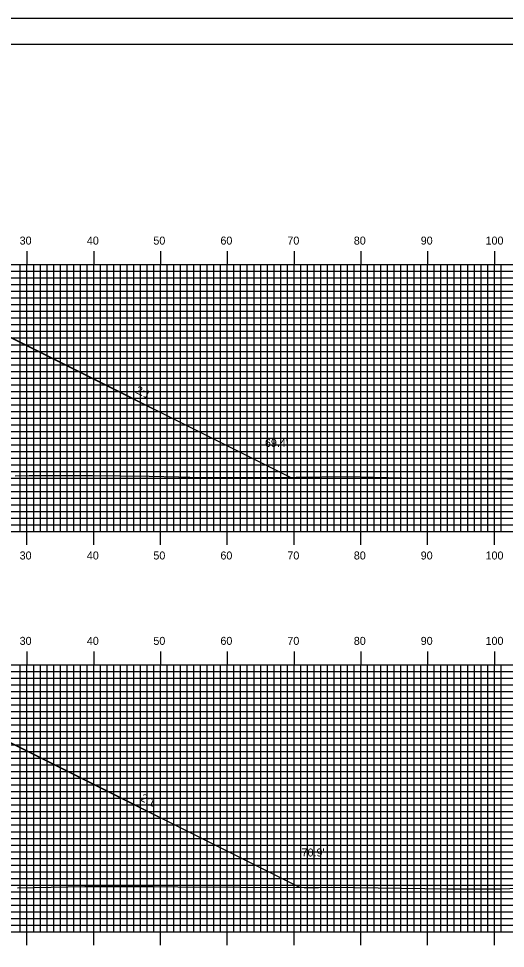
# Model space of a CAD drawing. Extents: x 1809800 to 1810143, y 442591 to 442811.
# Drawn here: x 1809994.1 to 1810067, y 442671.2 to 442810.5 of the extents above; entities that cross this region are included whole.
import ezdxf

# ---------------------------------------------------------------- set-up
doc = ezdxf.new("R2010")
doc.units = 0
for name, color, linetype in [('ANNOTATION', 7, 'Continuous'), ('BORDER', 7, 'Continuous'), ('D_Roadway_Centerline', 7, 'Continuous'), ('D_Roadway_SlopeLines', 7, 'Continuous'), ('D_Text_Standard', 7, 'Continuous'), ('H_V ANNOTATION', 7, 'Continuous'), ('MAJOR', 7, 'Continuous'), ('MINOR', 7, 'Continuous'), ('PLOT BOUNDARY', 7, 'Continuous'), ('S_Roadway_Centerline', 7, 'Continuous')]:
    doc.layers.add(name, color=color, linetype=linetype)

msp = doc.modelspace()

# ---------------------------------------------------------------- linework, layer by layer
at = {"layer": 'BORDER'}
msp.add_lwpolyline([(1809815.75, 442596.67), (1810135.75, 442596.67), (1810135.75, 442806.67), (1809815.75, 442806.67)], close=True, dxfattribs=at)
at = {"layer": 'D_Roadway_Centerline'}
for points in [[(1809892.44, 442741.52), (1809937.14, 442763.87), (1809942.35, 442766.48), (1809945.35, 442766.54), (1809953.35, 442766.7), (1809965.35, 442766.12), (1809977.35, 442765.54), (1809985.35, 442765.16), (1809988.35, 442765.02), (1809993.88, 442762.25), (1810034.75, 442741.82)], [(1809890.34, 442679.72), (1809937.14, 442703.12), (1809942.35, 442705.73), (1809945.35, 442705.79), (1809953.35, 442705.95), (1809965.35, 442705.37), (1809977.35, 442704.79), (1809985.35, 442704.41), (1809988.35, 442704.27), (1809993.88, 442701.5), (1810036.24, 442680.32)]]:
    msp.add_lwpolyline(points, dxfattribs=at)
at = {"layer": 'D_Roadway_SlopeLines'}
for points in [[(1809988.35, 442765.02), (1810034.75, 442741.82)], [(1809988.35, 442704.27), (1810036.24, 442680.32)]]:
    msp.add_lwpolyline(points, dxfattribs=at)
at = {"layer": 'MAJOR'}
for p, q in [((1809995.35, 442775.67), (1809995.35, 442773.67)), ((1810005.35, 442775.67), (1810005.35, 442773.67)), ((1810015.35, 442775.67), (1810015.35, 442773.67)), ((1810025.35, 442775.67), (1810025.35, 442773.67)), ((1810035.35, 442775.67), (1810035.35, 442773.67)), ((1810045.35, 442775.67), (1810045.35, 442773.67)), ((1810055.35, 442775.67), (1810055.35, 442773.67)), ((1810065.35, 442775.67), (1810065.35, 442773.67)), ((1809825.35, 442773.67), (1810105.35, 442773.67)), ((1809825.35, 442773.67), (1810105.35, 442773.67)), ((1809995.35, 442733.67), (1809995.35, 442773.67)), ((1810005.35, 442733.67), (1810005.35, 442773.67)), ((1810015.35, 442733.67), (1810015.35, 442773.67)), ((1810025.35, 442733.67), (1810025.35, 442773.67)), ((1810035.35, 442733.67), (1810035.35, 442773.67)), ((1810045.35, 442733.67), (1810045.35, 442773.67)), ((1810055.35, 442733.67), (1810055.35, 442773.67)), ((1810065.35, 442733.67), (1810065.35, 442773.67)), ((1809825.35, 442768.67), (1810105.35, 442768.67)), ((1809825.35, 442763.67), (1810105.35, 442763.67)), ((1809825.35, 442758.67), (1810105.35, 442758.67)), ((1809825.35, 442753.67), (1810105.35, 442753.67)), ((1809825.35, 442748.67), (1810105.35, 442748.67)), ((1809825.35, 442743.67), (1810105.35, 442743.67)), ((1809825.35, 442738.67), (1810105.35, 442738.67)), ((1809825.35, 442733.67), (1810105.35, 442733.67)), ((1809825.35, 442733.67), (1810105.35, 442733.67)), ((1809995.35, 442731.66), (1809995.35, 442733.67)), ((1810005.35, 442731.66), (1810005.35, 442733.67)), ((1810015.35, 442731.66), (1810015.35, 442733.67)), ((1810025.35, 442731.66), (1810025.35, 442733.67)), ((1810035.35, 442731.66), (1810035.35, 442733.67)), ((1810045.35, 442731.66), (1810045.35, 442733.67)), ((1810055.35, 442731.66), (1810055.35, 442733.67)), ((1810065.35, 442731.66), (1810065.35, 442733.67)), ((1809995.35, 442715.67), (1809995.35, 442713.67)), ((1810005.35, 442715.67), (1810005.35, 442713.67)), ((1810015.35, 442715.67), (1810015.35, 442713.67)), ((1810025.35, 442715.67), (1810025.35, 442713.67)), ((1810035.35, 442715.67), (1810035.35, 442713.67)), ((1810045.35, 442715.67), (1810045.35, 442713.67)), ((1810055.35, 442715.67), (1810055.35, 442713.67)), ((1810065.35, 442715.67), (1810065.35, 442713.67)), ((1809825.35, 442713.67), (1810105.35, 442713.67)), ((1809825.35, 442713.67), (1810105.35, 442713.67)), ((1809995.35, 442673.67), (1809995.35, 442713.67)), ((1810005.35, 442673.67), (1810005.35, 442713.67)), ((1810015.35, 442673.67), (1810015.35, 442713.67)), ((1810025.35, 442673.67), (1810025.35, 442713.67)), ((1810035.35, 442673.67), (1810035.35, 442713.67)), ((1810045.35, 442673.67), (1810045.35, 442713.67)), ((1810055.35, 442673.67), (1810055.35, 442713.67)), ((1810065.35, 442673.67), (1810065.35, 442713.67)), ((1809825.35, 442708.67), (1810105.35, 442708.67)), ((1809825.35, 442703.67), (1810105.35, 442703.67)), ((1809825.35, 442698.67), (1810105.35, 442698.67)), ((1809825.35, 442693.67), (1810105.35, 442693.67)), ((1809825.35, 442688.67), (1810105.35, 442688.67)), ((1809825.35, 442683.67), (1810105.35, 442683.67)), ((1809825.35, 442678.67), (1810105.35, 442678.67)), ((1809825.35, 442673.67), (1810105.35, 442673.67)), ((1809825.35, 442673.67), (1810105.35, 442673.67)), ((1809995.35, 442671.66), (1809995.35, 442673.67)), ((1810005.35, 442671.66), (1810005.35, 442673.67)), ((1810015.35, 442671.66), (1810015.35, 442673.67)), ((1810025.35, 442671.66), (1810025.35, 442673.67)), ((1810035.35, 442671.66), (1810035.35, 442673.67)), ((1810045.35, 442671.66), (1810045.35, 442673.67)), ((1810055.35, 442671.66), (1810055.35, 442673.67)), ((1810065.35, 442671.66), (1810065.35, 442673.67))]:
    msp.add_line(p, q, dxfattribs=at)
at = {"layer": 'MINOR'}
for p, q in [((1809994.35, 442733.67), (1809994.35, 442773.67)), ((1809996.35, 442733.67), (1809996.35, 442773.67)), ((1809997.35, 442733.67), (1809997.35, 442773.67)), ((1809998.35, 442733.67), (1809998.35, 442773.67)), ((1809999.35, 442733.67), (1809999.35, 442773.67)), ((1810000.35, 442733.67), (1810000.35, 442773.67)), ((1810001.35, 442733.67), (1810001.35, 442773.67)), ((1810002.35, 442733.67), (1810002.35, 442773.67)), ((1810003.35, 442733.67), (1810003.35, 442773.67)), ((1810004.35, 442733.67), (1810004.35, 442773.67)), ((1810006.35, 442733.67), (1810006.35, 442773.67)), ((1810007.35, 442733.67), (1810007.35, 442773.67)), ((1810008.35, 442733.67), (1810008.35, 442773.67)), ((1810009.35, 442733.67), (1810009.35, 442773.67)), ((1810010.35, 442733.67), (1810010.35, 442773.67)), ((1810011.35, 442733.67), (1810011.35, 442773.67)), ((1810012.35, 442733.67), (1810012.35, 442773.67)), ((1810013.35, 442733.67), (1810013.35, 442773.67)), ((1810014.35, 442733.67), (1810014.35, 442773.67)), ((1810016.35, 442733.67), (1810016.35, 442773.67)), ((1810017.35, 442733.67), (1810017.35, 442773.67)), ((1810018.35, 442733.67), (1810018.35, 442773.67)), ((1810019.35, 442733.67), (1810019.35, 442773.67)), ((1810020.35, 442733.67), (1810020.35, 442773.67)), ((1810021.35, 442733.67), (1810021.35, 442773.67)), ((1810022.35, 442733.67), (1810022.35, 442773.67)), ((1810023.35, 442733.67), (1810023.35, 442773.67)), ((1810024.35, 442733.67), (1810024.35, 442773.67)), ((1810026.35, 442733.67), (1810026.35, 442773.67)), ((1810027.35, 442733.67), (1810027.35, 442773.67)), ((1810028.35, 442733.67), (1810028.35, 442773.67)), ((1810029.35, 442733.67), (1810029.35, 442773.67)), ((1810030.35, 442733.67), (1810030.35, 442773.67)), ((1810031.35, 442733.67), (1810031.35, 442773.67)), ((1810032.35, 442733.67), (1810032.35, 442773.67)), ((1810033.35, 442733.67), (1810033.35, 442773.67)), ((1810034.35, 442733.67), (1810034.35, 442773.67)), ((1810036.35, 442733.67), (1810036.35, 442773.67)), ((1810037.35, 442733.67), (1810037.35, 442773.67)), ((1810038.35, 442733.67), (1810038.35, 442773.67)), ((1810039.35, 442733.67), (1810039.35, 442773.67)), ((1810040.35, 442733.67), (1810040.35, 442773.67)), ((1810041.35, 442733.67), (1810041.35, 442773.67)), ((1810042.35, 442733.67), (1810042.35, 442773.67)), ((1810043.35, 442733.67), (1810043.35, 442773.67)), ((1810044.35, 442733.67), (1810044.35, 442773.67)), ((1810046.35, 442733.67), (1810046.35, 442773.67)), ((1810047.35, 442733.67), (1810047.35, 442773.67)), ((1810048.35, 442733.67), (1810048.35, 442773.67)), ((1810049.35, 442733.67), (1810049.35, 442773.67)), ((1810050.35, 442733.67), (1810050.35, 442773.67)), ((1810051.35, 442733.67), (1810051.35, 442773.67)), ((1810052.35, 442733.67), (1810052.35, 442773.67)), ((1810053.35, 442733.67), (1810053.35, 442773.67)), ((1810054.35, 442733.67), (1810054.35, 442773.67)), ((1810056.35, 442733.67), (1810056.35, 442773.67)), ((1810057.35, 442733.67), (1810057.35, 442773.67)), ((1810058.35, 442733.67), (1810058.35, 442773.67)), ((1810059.35, 442733.67), (1810059.35, 442773.67)), ((1810060.35, 442733.67), (1810060.35, 442773.67)), ((1810061.35, 442733.67), (1810061.35, 442773.67)), ((1810062.35, 442733.67), (1810062.35, 442773.67)), ((1810063.35, 442733.67), (1810063.35, 442773.67)), ((1810064.35, 442733.67), (1810064.35, 442773.67)), ((1810066.35, 442733.67), (1810066.35, 442773.67)), ((1809825.35, 442772.67), (1810105.35, 442772.67)), ((1809825.35, 442771.67), (1810105.35, 442771.67)), ((1809825.35, 442770.67), (1810105.35, 442770.67)), ((1809825.35, 442769.67), (1810105.35, 442769.67)), ((1809825.35, 442767.67), (1810105.35, 442767.67)), ((1809825.35, 442766.67), (1810105.35, 442766.67)), ((1809825.35, 442765.67), (1810105.35, 442765.67)), ((1809825.35, 442764.67), (1810105.35, 442764.67)), ((1809825.35, 442762.67), (1810105.35, 442762.67)), ((1809825.35, 442761.67), (1810105.35, 442761.67)), ((1809825.35, 442760.67), (1810105.35, 442760.67)), ((1809825.35, 442759.67), (1810105.35, 442759.67)), ((1809825.35, 442757.67), (1810105.35, 442757.67)), ((1809825.35, 442756.67), (1810105.35, 442756.67)), ((1809825.35, 442755.67), (1810105.35, 442755.67)), ((1809825.35, 442754.67), (1810105.35, 442754.67)), ((1809825.35, 442752.67), (1810105.35, 442752.67)), ((1809825.35, 442751.67), (1810105.35, 442751.67)), ((1809825.35, 442750.67), (1810105.35, 442750.67)), ((1809825.35, 442749.67), (1810105.35, 442749.67)), ((1809825.35, 442747.67), (1810105.35, 442747.67)), ((1809825.35, 442746.67), (1810105.35, 442746.67)), ((1809825.35, 442745.67), (1810105.35, 442745.67)), ((1809825.35, 442744.67), (1810105.35, 442744.67)), ((1809825.35, 442742.67), (1810105.35, 442742.67)), ((1809825.35, 442741.67), (1810105.35, 442741.67)), ((1809825.35, 442740.67), (1810105.35, 442740.67)), ((1809825.35, 442739.67), (1810105.35, 442739.67)), ((1809825.35, 442737.67), (1810105.35, 442737.67)), ((1809825.35, 442736.67), (1810105.35, 442736.67)), ((1809825.35, 442735.67), (1810105.35, 442735.67)), ((1809825.35, 442734.67), (1810105.35, 442734.67)), ((1809994.35, 442673.67), (1809994.35, 442713.67)), ((1809996.35, 442673.67), (1809996.35, 442713.67)), ((1809997.35, 442673.67), (1809997.35, 442713.67)), ((1809998.35, 442673.67), (1809998.35, 442713.67)), ((1809999.35, 442673.67), (1809999.35, 442713.67)), ((1810000.35, 442673.67), (1810000.35, 442713.67)), ((1810001.35, 442673.67), (1810001.35, 442713.67)), ((1810002.35, 442673.67), (1810002.35, 442713.67)), ((1810003.35, 442673.67), (1810003.35, 442713.67)), ((1810004.35, 442673.67), (1810004.35, 442713.67)), ((1810006.35, 442673.67), (1810006.35, 442713.67)), ((1810007.35, 442673.67), (1810007.35, 442713.67)), ((1810008.35, 442673.67), (1810008.35, 442713.67)), ((1810009.35, 442673.67), (1810009.35, 442713.67)), ((1810010.35, 442673.67), (1810010.35, 442713.67)), ((1810011.35, 442673.67), (1810011.35, 442713.67)), ((1810012.35, 442673.67), (1810012.35, 442713.67)), ((1810013.35, 442673.67), (1810013.35, 442713.67)), ((1810014.35, 442673.67), (1810014.35, 442713.67)), ((1810016.35, 442673.67), (1810016.35, 442713.67)), ((1810017.35, 442673.67), (1810017.35, 442713.67)), ((1810018.35, 442673.67), (1810018.35, 442713.67)), ((1810019.35, 442673.67), (1810019.35, 442713.67)), ((1810020.35, 442673.67), (1810020.35, 442713.67)), ((1810021.35, 442673.67), (1810021.35, 442713.67)), ((1810022.35, 442673.67), (1810022.35, 442713.67)), ((1810023.35, 442673.67), (1810023.35, 442713.67)), ((1810024.35, 442673.67), (1810024.35, 442713.67)), ((1810026.35, 442673.67), (1810026.35, 442713.67)), ((1810027.35, 442673.67), (1810027.35, 442713.67)), ((1810028.35, 442673.67), (1810028.35, 442713.67)), ((1810029.35, 442673.67), (1810029.35, 442713.67)), ((1810030.35, 442673.67), (1810030.35, 442713.67)), ((1810031.35, 442673.67), (1810031.35, 442713.67)), ((1810032.35, 442673.67), (1810032.35, 442713.67)), ((1810033.35, 442673.67), (1810033.35, 442713.67)), ((1810034.35, 442673.67), (1810034.35, 442713.67)), ((1810036.35, 442673.67), (1810036.35, 442713.67)), ((1810037.35, 442673.67), (1810037.35, 442713.67)), ((1810038.35, 442673.67), (1810038.35, 442713.67)), ((1810039.35, 442673.67), (1810039.35, 442713.67)), ((1810040.35, 442673.67), (1810040.35, 442713.67)), ((1810041.35, 442673.67), (1810041.35, 442713.67)), ((1810042.35, 442673.67), (1810042.35, 442713.67)), ((1810043.35, 442673.67), (1810043.35, 442713.67)), ((1810044.35, 442673.67), (1810044.35, 442713.67)), ((1810046.35, 442673.67), (1810046.35, 442713.67)), ((1810047.35, 442673.67), (1810047.35, 442713.67)), ((1810048.35, 442673.67), (1810048.35, 442713.67)), ((1810049.35, 442673.67), (1810049.35, 442713.67)), ((1810050.35, 442673.67), (1810050.35, 442713.67)), ((1810051.35, 442673.67), (1810051.35, 442713.67)), ((1810052.35, 442673.67), (1810052.35, 442713.67)), ((1810053.35, 442673.67), (1810053.35, 442713.67)), ((1810054.35, 442673.67), (1810054.35, 442713.67)), ((1810056.35, 442673.67), (1810056.35, 442713.67)), ((1810057.35, 442673.67), (1810057.35, 442713.67)), ((1810058.35, 442673.67), (1810058.35, 442713.67)), ((1810059.35, 442673.67), (1810059.35, 442713.67)), ((1810060.35, 442673.67), (1810060.35, 442713.67)), ((1810061.35, 442673.67), (1810061.35, 442713.67)), ((1810062.35, 442673.67), (1810062.35, 442713.67)), ((1810063.35, 442673.67), (1810063.35, 442713.67)), ((1810064.35, 442673.67), (1810064.35, 442713.67)), ((1810066.35, 442673.67), (1810066.35, 442713.67)), ((1809825.35, 442712.67), (1810105.35, 442712.67)), ((1809825.35, 442711.67), (1810105.35, 442711.67)), ((1809825.35, 442710.67), (1810105.35, 442710.67)), ((1809825.35, 442709.67), (1810105.35, 442709.67)), ((1809825.35, 442707.67), (1810105.35, 442707.67)), ((1809825.35, 442706.67), (1810105.35, 442706.67)), ((1809825.35, 442705.67), (1810105.35, 442705.67)), ((1809825.35, 442704.67), (1810105.35, 442704.67)), ((1809825.35, 442702.67), (1810105.35, 442702.67)), ((1809825.35, 442701.67), (1810105.35, 442701.67)), ((1809825.35, 442700.67), (1810105.35, 442700.67)), ((1809825.35, 442699.67), (1810105.35, 442699.67)), ((1809825.35, 442697.67), (1810105.35, 442697.67)), ((1809825.35, 442696.67), (1810105.35, 442696.67)), ((1809825.35, 442695.67), (1810105.35, 442695.67)), ((1809825.35, 442694.67), (1810105.35, 442694.67)), ((1809825.35, 442692.67), (1810105.35, 442692.67)), ((1809825.35, 442691.67), (1810105.35, 442691.67)), ((1809825.35, 442690.67), (1810105.35, 442690.67)), ((1809825.35, 442689.67), (1810105.35, 442689.67)), ((1809825.35, 442687.67), (1810105.35, 442687.67)), ((1809825.35, 442686.67), (1810105.35, 442686.67)), ((1809825.35, 442685.67), (1810105.35, 442685.67)), ((1809825.35, 442684.67), (1810105.35, 442684.67)), ((1809825.35, 442682.67), (1810105.35, 442682.67)), ((1809825.35, 442681.67), (1810105.35, 442681.67)), ((1809825.35, 442680.67), (1810105.35, 442680.67)), ((1809825.35, 442679.67), (1810105.35, 442679.67)), ((1809825.35, 442677.67), (1810105.35, 442677.67)), ((1809825.35, 442676.67), (1810105.35, 442676.67)), ((1809825.35, 442675.67), (1810105.35, 442675.67)), ((1809825.35, 442674.67), (1810105.35, 442674.67))]:
    msp.add_line(p, q, dxfattribs=at)
at = {"layer": 'PLOT BOUNDARY'}
msp.add_lwpolyline([(1809799.56, 442590.55), (1810139.56, 442590.55), (1810139.56, 442810.55), (1809799.56, 442810.55)], close=True, dxfattribs=at)
at = {"layer": 'S_Roadway_Centerline'}
for points in [[(1809993.6, 442742), (1809995.7, 442742.05), (1810005.16, 442742.06), (1810013.66, 442741.94), (1810018.07, 442741.86), (1810021.46, 442741.74), (1810035.66, 442741.82), (1810043.28, 442741.89), (1810051.49, 442741.71), (1810059.59, 442741.63), (1810063.53, 442741.62), (1810067.32, 442741.54), (1810075.07, 442741.3), (1810083.13, 442741.11), (1810086.44, 442741.11), (1810090.1, 442741.14), (1810098.28, 442741.56), (1810105.2, 442741.75), (1810105.35, 442741.76)], [(1809993.93, 442680.26), (1810003.99, 442680.43), (1810014.37, 442680.43), (1810017.95, 442680.39), (1810036.88, 442680.32), (1810039.01, 442680.3), (1810040.95, 442680.35), (1810058.44, 442680.09), (1810066.22, 442680.11), (1810070.57, 442680.24), (1810081.23, 442680.08), (1810088.74, 442680.15), (1810096.97, 442680.62), (1810103.86, 442680.61), (1810105.35, 442680.63)]]:
    msp.add_lwpolyline(points, dxfattribs=at)

# ---------------------------------------------------------------- texts
at = {"layer": 'ANNOTATION'}
for p in [(1810011.48, 442754.49), (1810012.23, 442693.36)]:
    msp.add_text('2:1', height=1.2, rotation=333.4349, dxfattribs=at).set_placement(p)
at = {"layer": 'D_Text_Standard'}
for s, p in [("69.4'", (1810030.99, 442746.35)), ("70.9'", (1810036.48, 442684.95))]:
    msp.add_text(s, height=1.2, dxfattribs=at).set_placement(p)
at = {"layer": 'H_V ANNOTATION'}
for s, p in [('30', (1809994.25, 442776.67)), ('40', (1810004.32, 442776.67)), ('50', (1810014.28, 442776.67)), ('60', (1810024.32, 442776.67)), ('70', (1810034.35, 442776.67)), ('80', (1810044.3, 442776.67)), ('90', (1810054.32, 442776.67)), ('100', (1810064.03, 442776.67)), ('30', (1809994.25, 442729.47)), ('40', (1810004.32, 442729.47)), ('50', (1810014.28, 442729.47)), ('60', (1810024.32, 442729.47)), ('70', (1810034.35, 442729.47)), ('80', (1810044.3, 442729.47)), ('90', (1810054.32, 442729.47)), ('100', (1810064.03, 442729.47)), ('30', (1809994.25, 442716.67)), ('40', (1810004.32, 442716.67)), ('50', (1810014.28, 442716.67)), ('60', (1810024.32, 442716.67)), ('70', (1810034.35, 442716.67)), ('80', (1810044.3, 442716.67)), ('90', (1810054.32, 442716.67)), ('100', (1810064.03, 442716.67))]:
    msp.add_text(s, height=1.2, dxfattribs=at).set_placement(p)

doc.saveas('drawing.dxf')
